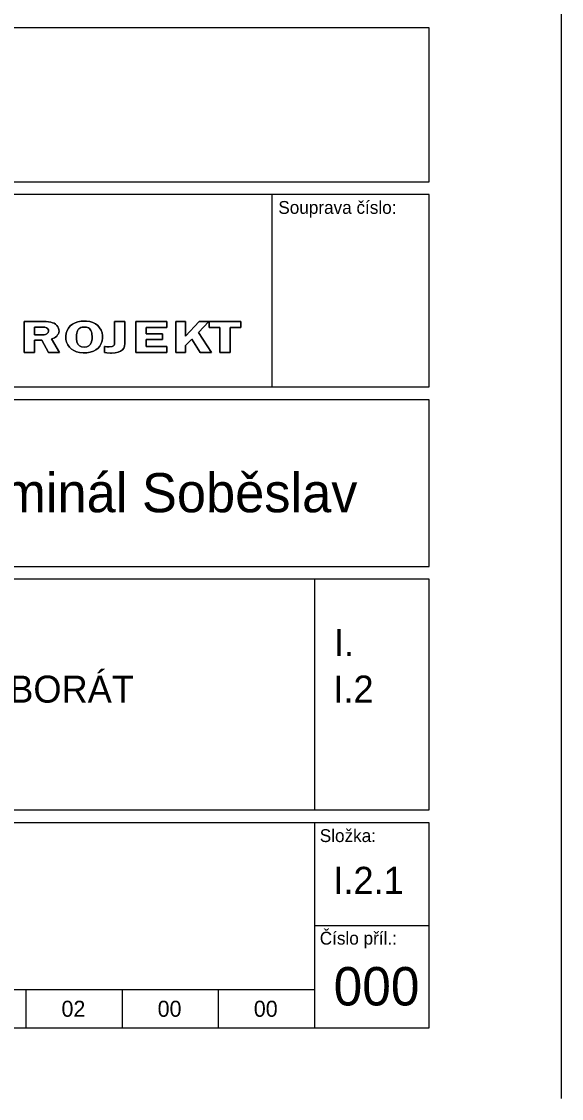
# Model space of a CAD drawing. Extents: x -876 to 174, y -298 to -1.
# Drawn here: x 98 to 173.8, y -298.1 to -146.9 of the extents above; entities that cross this region are included whole.
import ezdxf

# ---------------------------------------------------------------- set-up
doc = ezdxf.new("R2010")
doc.units = 0
doc.layers.add('Nabyvatel_1_SZ_zábor', color=7, linetype='Continuous')
doc.layers.add('Nabyvatel_2_Město_zábor', color=7, linetype='Continuous')

msp = doc.modelspace()

# ---------------------------------------------------------------- linework, layer by layer
at = {"layer": 'Nabyvatel_1_SZ_zábor'}
msp.add_lwpolyline([(173.79, -298.13), (173.79, -1.13)], dxfattribs=at)
at = {"layer": 'Nabyvatel_2_Město_zábor'}
for p, q in [((114.04, -193.4), (114.04, -189.05)), ((114.04, -189.05), (118.38, -189.05)), ((115.49, -189.88), (115.49, -190.77)), ((118.38, -189.88), (115.49, -189.88)), ((118.38, -189.05), (118.38, -189.88)), ((119.63, -193.4), (119.63, -189.05)), ((119.63, -189.05), (121.02, -189.05)), ((121.02, -191.1), (122.92, -189.05)), ((121.02, -189.05), (121.02, -191.1)), ((124.28, -189.05), (122.83, -190.6)), ((122.92, -189.05), (124.28, -189.05)), ((124.34, -189.91), (124.34, -189.05)), ((124.34, -189.05), (128.79, -189.05)), ((125.85, -189.91), (124.34, -189.91)), ((125.85, -193.4), (125.85, -189.91)), ((128.79, -189.91), (127.29, -189.91)), ((127.29, -189.91), (127.29, -193.4)), ((128.79, -189.05), (128.79, -189.91)), ((115.49, -190.77), (117.76, -190.77)), ((117.76, -191.59), (115.49, -191.59)), ((115.49, -191.59), (115.49, -192.54)), ((117.76, -190.77), (117.76, -191.59)), ((121.88, -191.52), (121.02, -192.4)), ((123.08, -193.4), (121.88, -191.52)), ((122.83, -190.6), (124.64, -193.4)), ((118.38, -193.4), (114.04, -193.4)), ((115.49, -192.54), (118.38, -192.54)), ((118.38, -192.54), (118.38, -193.4)), ((121.02, -193.4), (119.63, -193.4)), ((121.02, -192.4), (121.02, -193.4)), ((124.64, -193.4), (123.08, -193.4)), ((127.29, -193.4), (125.85, -193.4))]:
    msp.add_line(p, q, dxfattribs=at)
for points in [[(155.22, -169.43), (155.22, -147.83), (-15.78, -147.83), (-15.78, -169.43)], [(-15.78, -198.23), (155.22, -198.23), (155.22, -171.23), (-15.78, -171.23)], [(108.68, -189.62), (108.94, -189.92), (109.15, -190.25), (109.29, -190.62), (109.36, -191), (109.37, -191.39), (109.31, -191.78), (109.18, -192.15), (108.99, -192.49), (108.74, -192.79), (108.44, -193.04), (108.07, -193.23), (107.63, -193.37), (107.16, -193.45), (106.64, -193.46), (106.15, -193.42), (105.71, -193.31), (105.32, -193.14), (104.99, -192.92), (104.7, -192.63), (104.48, -192.3), (104.32, -191.95), (104.23, -191.56), (104.21, -191.37), (104.2, -191.26), (104.2, -191.1), (104.26, -190.68), (104.39, -190.3), (104.58, -189.96), (104.83, -189.67), (105.14, -189.42), (105.5, -189.23), (105.91, -189.09), (106.37, -189.01), (106.84, -188.98), (107.1, -188.99), (107.58, -189.06), (108.01, -189.18), (108.37, -189.37)], [(102.08, -189.13), (102.33, -189.21), (102.55, -189.3), (102.76, -189.44), (102.94, -189.6), (103.08, -189.79), (103.19, -189.99), (103.24, -190.21), (103.25, -190.42), (103.22, -190.6), (103.16, -190.78), (103.06, -190.94), (102.93, -191.1), (102.76, -191.23), (102.61, -191.33), (102.4, -191.42), (102.26, -191.47), (102.21, -191.48), (103.33, -193.4), (101.76, -193.4), (100.83, -191.68), (99.81, -191.68), (99.81, -193.4), (98.38, -193.4), (98.38, -189.05), (101.05, -189.05), (101.45, -189.06), (101.79, -189.09)], [(100.53, -190.94), (100.82, -190.93), (101.15, -190.92), (101.36, -190.88), (101.56, -190.77), (101.72, -190.6), (101.79, -190.39), (101.76, -190.2), (101.65, -190.04), (101.48, -189.92), (101.28, -189.85), (100.95, -189.83), (100.59, -189.83), (99.81, -189.83), (99.81, -190.94)], [(105.95, -190.19), (105.86, -190.34), (105.8, -190.51), (105.74, -190.7), (105.71, -190.9), (105.69, -191.11), (105.69, -191.47), (105.77, -191.89), (105.91, -192.22), (106.13, -192.45), (106.43, -192.59), (106.79, -192.64), (107.16, -192.59), (107.45, -192.46), (107.67, -192.22), (107.81, -191.9), (107.89, -191.48), (107.89, -191.11), (107.87, -190.88), (107.84, -190.67), (107.79, -190.49), (107.72, -190.32), (107.63, -190.17), (107.53, -190.05), (107.4, -189.95), (107.26, -189.88), (107.09, -189.84), (106.91, -189.82), (106.7, -189.82), (106.5, -189.84), (106.33, -189.89), (106.18, -189.97), (106.05, -190.07)], [(112.44, -192.51), (112.33, -192.8), (112.15, -193.04), (111.9, -193.23), (111.56, -193.36), (111.14, -193.44), (110.64, -193.47), (110.56, -193.47), (110.53, -193.47), (110.46, -193.47), (109.97, -193.44), (109.62, -193.4), (109.62, -192.56), (109.72, -192.57), (109.96, -192.6), (110.31, -192.61), (110.72, -192.55), (110.88, -192.48), (110.98, -192.39), (111.05, -192.21), (111.06, -192.07), (111.06, -192.01), (111.06, -189.05), (112.48, -189.05), (112.48, -192.15)], [(-15.78, -223.43), (155.22, -223.43), (155.22, -200.03), (-15.78, -200.03)], [(-15.78, -257.63), (155.22, -257.63), (155.22, -225.23), (-15.78, -225.23)], [(-15.78, -288.23), (155.22, -288.23), (155.22, -259.43), (-15.78, -259.43)]]:
    msp.add_lwpolyline(points, close=True, dxfattribs=at)
for points in [[(133.14, -171.23), (133.14, -198.23)], [(109.36, -191), (109.29, -190.62), (109.15, -190.25), (108.94, -189.92), (108.68, -189.62), (108.37, -189.37), (108.01, -189.18), (107.58, -189.06), (107.1, -188.99), (106.84, -188.98), (106.37, -189.01), (105.91, -189.09), (105.5, -189.23), (105.14, -189.42), (104.83, -189.67), (104.58, -189.96), (104.39, -190.3), (104.26, -190.68), (104.2, -191.1), (104.2, -191.26), (104.21, -191.37), (104.23, -191.56), (104.32, -191.95), (104.48, -192.3), (104.7, -192.63), (104.99, -192.92), (105.32, -193.14), (105.71, -193.31), (106.15, -193.42), (106.64, -193.46), (107.16, -193.45), (107.63, -193.37), (108.07, -193.23), (108.44, -193.04), (108.74, -192.79), (108.99, -192.49), (109.18, -192.15), (109.31, -191.78), (109.37, -191.39), (109.36, -191)], [(103.16, -190.78), (103.22, -190.6), (103.25, -190.42), (103.24, -190.21), (103.19, -189.99), (103.08, -189.79), (102.94, -189.6), (102.76, -189.44), (102.55, -189.3), (102.33, -189.21), (102.08, -189.13), (101.79, -189.09), (101.45, -189.06), (101.05, -189.05), (98.38, -189.05), (98.38, -193.4), (99.81, -193.4), (99.81, -191.68), (100.83, -191.68), (101.76, -193.4), (103.33, -193.4), (102.21, -191.48), (102.26, -191.47), (102.4, -191.42), (102.61, -191.33), (102.76, -191.23), (102.93, -191.1), (103.06, -190.94), (103.16, -190.78)], [(99.81, -189.83), (100.59, -189.83), (100.95, -189.83), (101.28, -189.85), (101.48, -189.92), (101.65, -190.04), (101.76, -190.2), (101.79, -190.39), (101.72, -190.6), (101.56, -190.77), (101.36, -190.88), (101.15, -190.92), (100.82, -190.93), (100.53, -190.94), (99.81, -190.94), (99.81, -189.83)], [(105.69, -191.11), (105.71, -190.9), (105.74, -190.7), (105.8, -190.51), (105.86, -190.34), (105.95, -190.19), (106.05, -190.07), (106.18, -189.97), (106.33, -189.89), (106.5, -189.84), (106.7, -189.82), (106.91, -189.82), (107.09, -189.84), (107.26, -189.88), (107.4, -189.95), (107.53, -190.05), (107.63, -190.17), (107.72, -190.32), (107.79, -190.49), (107.84, -190.67), (107.87, -190.88), (107.89, -191.11), (107.89, -191.48), (107.81, -191.9), (107.67, -192.22), (107.45, -192.46), (107.16, -192.59), (106.79, -192.64), (106.43, -192.59), (106.13, -192.45), (105.91, -192.22), (105.77, -191.89), (105.69, -191.47), (105.69, -191.11)], [(112.48, -189.05), (111.06, -189.05), (111.06, -192.07), (111.05, -192.21), (110.98, -192.39), (110.88, -192.48), (110.72, -192.55), (110.31, -192.61), (109.96, -192.6), (109.72, -192.57), (109.62, -192.56), (109.62, -193.4), (109.97, -193.44), (110.46, -193.47), (110.53, -193.47), (110.56, -193.47), (110.64, -193.47), (111.14, -193.44), (111.56, -193.36), (111.9, -193.23), (112.15, -193.04), (112.33, -192.8), (112.44, -192.51), (112.48, -192.15), (112.48, -189.05)], [(117.76, -190.77), (115.49, -190.77), (115.49, -189.88), (118.38, -189.88), (118.38, -189.05), (114.04, -189.05), (114.04, -193.4), (118.38, -193.4), (118.38, -192.54), (115.49, -192.54), (115.49, -191.59), (117.76, -191.59), (117.76, -190.77)], [(121.02, -189.05), (119.63, -189.05), (119.63, -193.4), (121.02, -193.4), (121.02, -192.4), (121.88, -191.52), (123.08, -193.4), (124.64, -193.4), (122.83, -190.6), (124.28, -189.05), (122.92, -189.05), (121.02, -191.1), (121.02, -189.05)], [(127.29, -189.91), (128.79, -189.91), (128.79, -189.05), (124.34, -189.05), (124.34, -189.91), (125.85, -189.91), (125.85, -193.4), (127.29, -193.4), (127.29, -189.91)], [(-15.78, -198.23), (155.22, -198.23)], [(139.1, -225.23), (139.1, -257.63)], [(139.1, -259.43), (139.1, -288.23)], [(139.1, -273.83), (155.22, -273.83)], [(37.71, -282.83), (139.1, -282.83)], [(98.6, -282.83), (98.6, -288.23)], [(112.1, -282.83), (112.1, -288.23)], [(125.6, -282.83), (125.6, -288.23)]]:
    msp.add_lwpolyline(points, dxfattribs=at)

# ---------------------------------------------------------------- texts
for s, height, p in [('Souprava číslo:', 1.8, (134.04, -173.93)), ('Přestupní terminál Soběslav', 5.5, (53.17, -215.83)), ('I.', 3.8, (141.86, -236.03)), ('MAJETKOPRÁVNÍ ELABORÁT', 3.8, (42.33, -242.56)), ('I.2', 3.8, (141.77, -242.56)), ('Složka:', 1.8, (139.86, -262.13)), ('I.2.1', 3.8, (141.77, -269.41)), ('Číslo příl.:', 1.8, (139.86, -276.53)), ('000', 5.4, (141.81, -285.08)), ('02', 2.25, (103.6, -286.66)), ('00', 2.25, (117.1, -286.66)), ('00', 2.25, (130.6, -286.66))]:
    msp.add_text(s, height=height, dxfattribs=at).set_placement(p)

doc.saveas('drawing.dxf')
